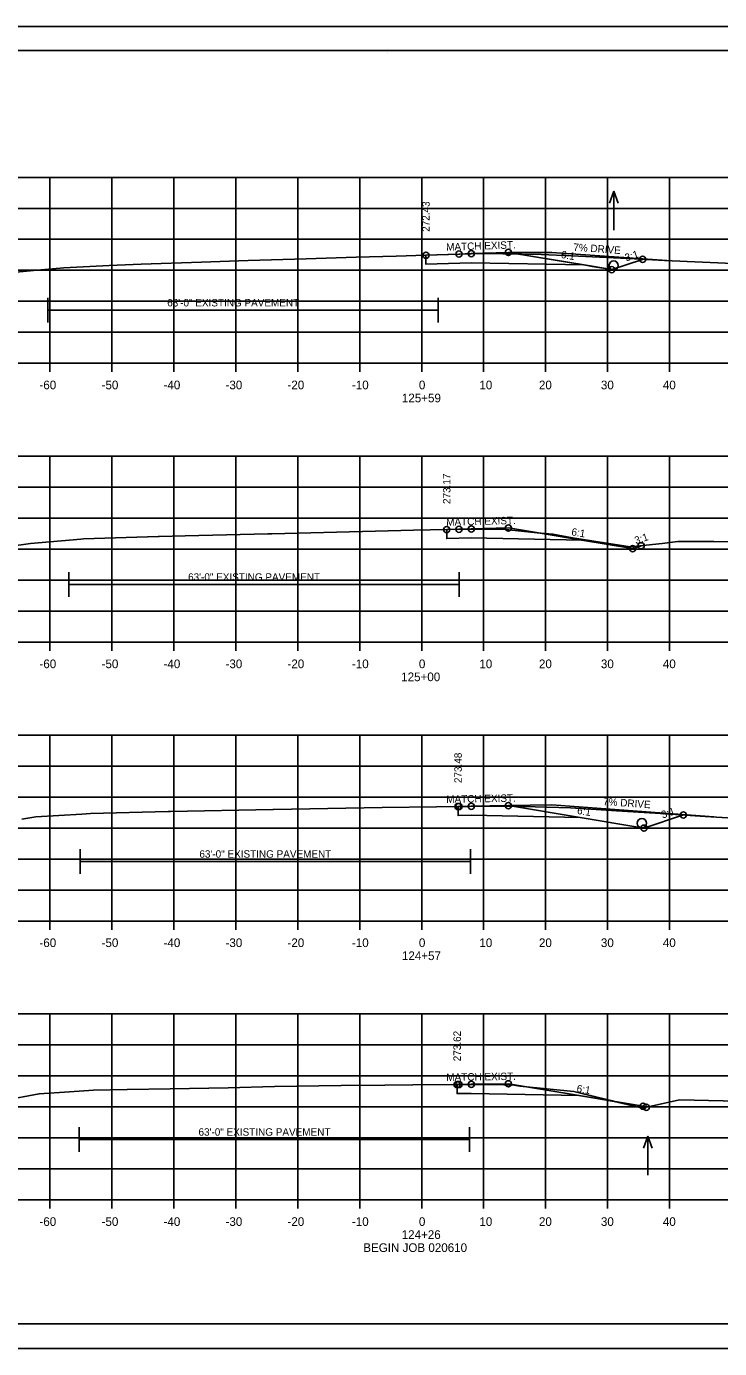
# Model space of a CAD drawing. Extents: x 1103485 to 1107180, y 2010593 to 2011873.
# Drawn here: x 1106953.4 to 1107065.3, y 2010592.8 to 2010806.2 of the extents above; entities that cross this region are included whole.
import ezdxf

# ---------------------------------------------------------------- set-up
doc = ezdxf.new("R2010")
doc.units = 0
for name, color, linetype in [('R_Alt Surface', 7, 'Continuous'), ('R_Axis', 7, 'Continuous'), ('R_Axis Annot', 7, 'Continuous'), ('R_Border', 7, 'Continuous'), ('R_Contours', 7, 'Continuous'), ('R_Dimension', 7, 'Continuous'), ('R_Drive', 7, 'Continuous'), ('R_Exist Surface', 7, 'Continuous'), ('R_Fin Surface', 7, 'Continuous'), ('R_Grid', 7, 'Continuous'), ('R_No Plot', 7, 'Continuous'), ('R_Proposed Const Limits', 7, 'Continuous'), ('R_Water', 7, 'Continuous'), ('R_Water Annot', 7, 'Continuous'), ('R_Xsect Elev', 7, 'Continuous'), ('R_Xsect Slope', 7, 'Continuous')]:
    doc.layers.add(name, color=color, linetype=linetype)

msp = doc.modelspace()

# ---------------------------------------------------------------- linework, layer by layer
at = {"layer": 'R_Alt Surface'}
for points in [[(1107017.86, 2010769.25), (1107017.86, 2010767.79), (1107025.18, 2010768.04), (1107043.38, 2010767.68)], [(1107021.22, 2010724.99), (1107021.22, 2010723.53), (1107025.18, 2010723.63), (1107043.02, 2010723.27)], [(1107023.05, 2010680.3), (1107023.05, 2010678.84), (1107025.18, 2010678.88), (1107042.73, 2010678.53)], [(1107022.9, 2010635.43), (1107022.9, 2010633.97), (1107025.18, 2010634.01), (1107042.6, 2010633.66)]]:
    msp.add_lwpolyline(points, dxfattribs=at)
at = {"layer": 'R_Axis'}
for p, q in [((1106867.18, 2010751.82), (1107167.18, 2010751.82)), ((1106957.18, 2010750.42), (1106957.18, 2010751.82)), ((1106967.18, 2010750.42), (1106967.18, 2010751.82)), ((1106977.18, 2010750.42), (1106977.18, 2010751.82)), ((1106987.18, 2010750.42), (1106987.18, 2010751.82)), ((1106997.18, 2010750.42), (1106997.18, 2010751.82)), ((1107007.18, 2010750.42), (1107007.18, 2010751.82)), ((1107017.18, 2010750.42), (1107017.18, 2010751.82)), ((1107027.18, 2010750.42), (1107027.18, 2010751.82)), ((1107037.18, 2010750.42), (1107037.18, 2010751.82)), ((1107047.18, 2010750.42), (1107047.18, 2010751.82)), ((1107057.18, 2010750.42), (1107057.18, 2010751.82)), ((1106867.18, 2010706.82), (1107167.18, 2010706.82)), ((1106957.18, 2010705.42), (1106957.18, 2010706.82)), ((1106967.18, 2010705.42), (1106967.18, 2010706.82)), ((1106977.18, 2010705.42), (1106977.18, 2010706.82)), ((1106987.18, 2010705.42), (1106987.18, 2010706.82)), ((1106997.18, 2010705.42), (1106997.18, 2010706.82)), ((1107007.18, 2010705.42), (1107007.18, 2010706.82)), ((1107017.18, 2010705.42), (1107017.18, 2010706.82)), ((1107027.18, 2010705.42), (1107027.18, 2010706.82)), ((1107037.18, 2010705.42), (1107037.18, 2010706.82)), ((1107047.18, 2010705.42), (1107047.18, 2010706.82)), ((1107057.18, 2010705.42), (1107057.18, 2010706.82)), ((1106867.18, 2010661.82), (1107167.18, 2010661.82)), ((1106957.18, 2010660.42), (1106957.18, 2010661.82)), ((1106967.18, 2010660.42), (1106967.18, 2010661.82)), ((1106977.18, 2010660.42), (1106977.18, 2010661.82)), ((1106987.18, 2010660.42), (1106987.18, 2010661.82)), ((1106997.18, 2010660.42), (1106997.18, 2010661.82)), ((1107007.18, 2010660.42), (1107007.18, 2010661.82)), ((1107017.18, 2010660.42), (1107017.18, 2010661.82)), ((1107027.18, 2010660.42), (1107027.18, 2010661.82)), ((1107037.18, 2010660.42), (1107037.18, 2010661.82)), ((1107047.18, 2010660.42), (1107047.18, 2010661.82)), ((1107057.18, 2010660.42), (1107057.18, 2010661.82)), ((1106867.18, 2010616.82), (1107167.18, 2010616.82)), ((1106957.18, 2010615.42), (1106957.18, 2010616.82)), ((1106967.18, 2010615.42), (1106967.18, 2010616.82)), ((1106977.18, 2010615.42), (1106977.18, 2010616.82)), ((1106987.18, 2010615.42), (1106987.18, 2010616.82)), ((1106997.18, 2010615.42), (1106997.18, 2010616.82)), ((1107007.18, 2010615.42), (1107007.18, 2010616.82)), ((1107017.18, 2010615.42), (1107017.18, 2010616.82)), ((1107027.18, 2010615.42), (1107027.18, 2010616.82)), ((1107037.18, 2010615.42), (1107037.18, 2010616.82)), ((1107047.18, 2010615.42), (1107047.18, 2010616.82)), ((1107057.18, 2010615.42), (1107057.18, 2010616.82))]:
    msp.add_line(p, q, dxfattribs=at)
at = {"layer": 'R_Border'}
for p, q in [((1106859.18, 2010802.28), (1107175.36, 2010802.28)), ((1107011.7, 2010802.02), (1107011.7, 2010802.02)), ((1107011.7, 2010802.02), (1107011.7, 2010802.02)), ((1107175.36, 2010596.82), (1106859.18, 2010596.82))]:
    msp.add_line(p, q, dxfattribs=at)
at = {"layer": 'R_Contours'}
for points in [[(1107017.86, 2010769.25), (1107026.97, 2010769.51), (1107027.06, 2010769.51), (1107027.15, 2010769.51), (1107036.46, 2010769.36), (1107041.33, 2010769.13), (1107051.53, 2010768.65), (1107052.83, 2010768.59), (1107047.86, 2010766.93), (1107044.67, 2010767.46), (1107043.38, 2010767.68), (1107025.18, 2010768.04), (1107017.86, 2010767.79)], [(1107021.22, 2010724.99), (1107021.41, 2010724.99), (1107030.24, 2010725.06), (1107035.8, 2010724.48), (1107038.36, 2010724.27), (1107041.52, 2010723.64), (1107050.8, 2010722.18), (1107052.6, 2010722.37), (1107051.22, 2010721.91), (1107043.02, 2010723.27), (1107025.18, 2010723.63), (1107021.22, 2010723.53)], [(1107023.05, 2010680.3), (1107023.11, 2010680.3), (1107024.86, 2010680.31), (1107031.29, 2010680.35), (1107031.7, 2010680.34), (1107041.21, 2010680.08), (1107048.6, 2010679.62), (1107055.7, 2010679.17), (1107059.42, 2010678.93), (1107053.05, 2010676.81), (1107042.73, 2010678.53), (1107025.18, 2010678.88), (1107023.05, 2010678.84)], [(1107022.9, 2010635.43), (1107030.45, 2010635.39), (1107031.71, 2010635.37), (1107033.03, 2010635.19), (1107041.76, 2010634.29), (1107048.22, 2010632.72), (1107042.6, 2010633.66), (1107025.18, 2010634.01), (1107022.9, 2010633.97)], [(1107048.22, 2010632.72), (1107051.97, 2010631.82), (1107052.79, 2010631.64), (1107053.23, 2010631.73), (1107053.42, 2010631.77), (1107052.9, 2010631.94)]]:
    msp.add_lwpolyline(points, close=True, dxfattribs=at)
at = {"layer": 'R_Dimension'}
for p, q in [((1106956.86, 2010762.39), (1106956.86, 2010758.39)), ((1107019.86, 2010762.39), (1107019.86, 2010758.39)), ((1106956.86, 2010760.39), (1107019.86, 2010760.39)), ((1106960.22, 2010718.13), (1106960.22, 2010714.13)), ((1107023.22, 2010718.13), (1107023.22, 2010714.13)), ((1106960.22, 2010716.13), (1107023.22, 2010716.13)), ((1106962.05, 2010673.44), (1106962.05, 2010669.44)), ((1107025.05, 2010673.44), (1107025.05, 2010669.44)), ((1106962.05, 2010671.44), (1107025.05, 2010671.44)), ((1106961.9, 2010628.58), (1106961.9, 2010624.58)), ((1107024.9, 2010628.58), (1107024.9, 2010624.58)), ((1106961.9, 2010626.58), (1107024.9, 2010626.58))]:
    msp.add_line(p, q, dxfattribs=at)
at = {"layer": 'R_Drive'}
for p, q in [((1107031.18, 2010769.71), (1107038.18, 2010769.71)), ((1107038.18, 2010769.71), (1107056.73, 2010768.42)), ((1107031.18, 2010680.45), (1107038.18, 2010680.58)), ((1107038.18, 2010680.58), (1107064.33, 2010678.62))]:
    msp.add_line(p, q, dxfattribs=at)
at = {"layer": 'R_Exist Surface'}
for points in [[(1106951.15, 2010766.45), (1106955.12, 2010766.83), (1106959.41, 2010767.22), (1106966.72, 2010767.59), (1106971.9, 2010767.83), (1106981.66, 2010768.15), (1106989.15, 2010768.38), (1106998.52, 2010768.68), (1107006.6, 2010768.92), (1107013.05, 2010769.1), (1107017.86, 2010769.25), (1107026.97, 2010769.51), (1107027.06, 2010769.51), (1107027.15, 2010769.51), (1107036.46, 2010769.36), (1107041.33, 2010769.13), (1107051.53, 2010768.65), (1107056.34, 2010768.43), (1107068.63, 2010767.86)], [(1106946.71, 2010721.7), (1106954.05, 2010722.75), (1106962.19, 2010723.44), (1106962.6, 2010723.48), (1106974.67, 2010723.88), (1106974.79, 2010723.88), (1106979.01, 2010723.98), (1106992.35, 2010724.31), (1106993.01, 2010724.32), (1107009.71, 2010724.73), (1107015.88, 2010724.87), (1107021.22, 2010724.99), (1107021.41, 2010724.99), (1107030.24, 2010725.06), (1107035.8, 2010724.48), (1107038.36, 2010724.27), (1107041.52, 2010723.64), (1107050.8, 2010722.18), (1107055.98, 2010722.72), (1107058.5, 2010723.08), (1107064.31, 2010723.05), (1107073.05, 2010722.93)], [(1106952.63, 2010678.25), (1106954.9, 2010678.62), (1106962.32, 2010679.09), (1106963.74, 2010679.19), (1106976.28, 2010679.48), (1106976.44, 2010679.49), (1106976.66, 2010679.49), (1106993.16, 2010679.79), (1106993.26, 2010679.79), (1107010.81, 2010680.16), (1107019.56, 2010680.26), (1107023.05, 2010680.3), (1107023.11, 2010680.3), (1107024.86, 2010680.31), (1107031.29, 2010680.35), (1107031.7, 2010680.34), (1107041.21, 2010680.08), (1107048.6, 2010679.62), (1107055.7, 2010679.17), (1107062.95, 2010678.71), (1107070.17, 2010678.25)], [(1106949.69, 2010632.86), (1106955.43, 2010633.96), (1106960.33, 2010634.27), (1106964.21, 2010634.51), (1106969.63, 2010634.61), (1106976.57, 2010634.74), (1106985.95, 2010634.93), (1106993.44, 2010635.1), (1107004.2, 2010635.28), (1107011.22, 2010635.36), (1107015.74, 2010635.38), (1107022.9, 2010635.43), (1107030.45, 2010635.39), (1107031.71, 2010635.37), (1107033.03, 2010635.19), (1107041.76, 2010634.29), (1107051.97, 2010631.82), (1107052.79, 2010631.64), (1107053.23, 2010631.73), (1107058.8, 2010632.98), (1107070.52, 2010632.72)]]:
    msp.add_lwpolyline(points, dxfattribs=at)
at = {"layer": 'R_Fin Surface'}
for points in [[(1107017.86, 2010769.25), (1107023.18, 2010769.44), (1107025.18, 2010769.51), (1107031.18, 2010769.71), (1107043.38, 2010767.68), (1107047.86, 2010766.93), (1107052.83, 2010768.59)], [(1107017.86, 2010769.25), (1107023.18, 2010769.44), (1107025.18, 2010769.51), (1107031.18, 2010769.71)], [(1107021.22, 2010724.99), (1107023.18, 2010725.04), (1107025.18, 2010725.09), (1107031.18, 2010725.25), (1107043.02, 2010723.27), (1107051.22, 2010721.91), (1107052.6, 2010722.37)], [(1107021.22, 2010724.99), (1107023.18, 2010725.04), (1107025.18, 2010725.09), (1107031.18, 2010725.25)], [(1107023.05, 2010680.3), (1107023.18, 2010680.3), (1107025.18, 2010680.34), (1107031.18, 2010680.45), (1107042.73, 2010678.53), (1107053.05, 2010676.81), (1107059.42, 2010678.93)], [(1107023.05, 2010680.3), (1107023.18, 2010680.3), (1107025.18, 2010680.34), (1107031.18, 2010680.45)], [(1107022.9, 2010635.43), (1107023.18, 2010635.44), (1107025.18, 2010635.47), (1107031.18, 2010635.56), (1107042.6, 2010633.66), (1107052.9, 2010631.94), (1107053.42, 2010631.77)], [(1107022.9, 2010635.43), (1107023.18, 2010635.44), (1107025.18, 2010635.47), (1107031.18, 2010635.56)]]:
    msp.add_lwpolyline(points, dxfattribs=at)
at = {"layer": 'R_Grid'}
for p, q in [((1106867.18, 2010781.82), (1107167.18, 2010781.82)), ((1106957.18, 2010751.82), (1106957.18, 2010781.82)), ((1106967.18, 2010751.82), (1106967.18, 2010781.82)), ((1106977.18, 2010751.82), (1106977.18, 2010781.82)), ((1106987.18, 2010751.82), (1106987.18, 2010781.82)), ((1106997.18, 2010751.82), (1106997.18, 2010781.82)), ((1107007.18, 2010751.82), (1107007.18, 2010781.82)), ((1107017.18, 2010751.82), (1107017.18, 2010781.82)), ((1107027.18, 2010751.82), (1107027.18, 2010781.82)), ((1107037.18, 2010751.82), (1107037.18, 2010781.82)), ((1107047.18, 2010751.82), (1107047.18, 2010781.82)), ((1107057.18, 2010751.82), (1107057.18, 2010781.82)), ((1106867.18, 2010776.82), (1107167.18, 2010776.82)), ((1106867.18, 2010771.82), (1107167.18, 2010771.82)), ((1106867.18, 2010766.82), (1107167.18, 2010766.82)), ((1106867.18, 2010761.82), (1107167.18, 2010761.82)), ((1106867.18, 2010756.82), (1107167.18, 2010756.82)), ((1106867.18, 2010751.82), (1107167.18, 2010751.82)), ((1106867.18, 2010736.82), (1107167.18, 2010736.82)), ((1106957.18, 2010706.82), (1106957.18, 2010736.82)), ((1106967.18, 2010706.82), (1106967.18, 2010736.82)), ((1106977.18, 2010706.82), (1106977.18, 2010736.82)), ((1106987.18, 2010706.82), (1106987.18, 2010736.82)), ((1106997.18, 2010706.82), (1106997.18, 2010736.82)), ((1107007.18, 2010706.82), (1107007.18, 2010736.82)), ((1107017.18, 2010706.82), (1107017.18, 2010736.82)), ((1107027.18, 2010706.82), (1107027.18, 2010736.82)), ((1107037.18, 2010706.82), (1107037.18, 2010736.82)), ((1107047.18, 2010706.82), (1107047.18, 2010736.82)), ((1107057.18, 2010706.82), (1107057.18, 2010736.82)), ((1106867.18, 2010731.82), (1107167.18, 2010731.82)), ((1106867.18, 2010726.82), (1107167.18, 2010726.82)), ((1106867.18, 2010721.82), (1107167.18, 2010721.82)), ((1106867.18, 2010716.82), (1107167.18, 2010716.82)), ((1106867.18, 2010711.82), (1107167.18, 2010711.82)), ((1106867.18, 2010706.82), (1107167.18, 2010706.82)), ((1106867.18, 2010691.82), (1107167.18, 2010691.82)), ((1106957.18, 2010661.82), (1106957.18, 2010691.82)), ((1106967.18, 2010661.82), (1106967.18, 2010691.82)), ((1106977.18, 2010661.82), (1106977.18, 2010691.82)), ((1106987.18, 2010661.82), (1106987.18, 2010691.82)), ((1106997.18, 2010661.82), (1106997.18, 2010691.82)), ((1107007.18, 2010661.82), (1107007.18, 2010691.82)), ((1107017.18, 2010661.82), (1107017.18, 2010691.82)), ((1107027.18, 2010661.82), (1107027.18, 2010691.82)), ((1107037.18, 2010661.82), (1107037.18, 2010691.82)), ((1107047.18, 2010661.82), (1107047.18, 2010691.82)), ((1107057.18, 2010661.82), (1107057.18, 2010691.82)), ((1106867.18, 2010686.82), (1107167.18, 2010686.82)), ((1106867.18, 2010681.82), (1107167.18, 2010681.82)), ((1106867.18, 2010676.82), (1107167.18, 2010676.82)), ((1106867.18, 2010671.82), (1107167.18, 2010671.82)), ((1106867.18, 2010666.82), (1107167.18, 2010666.82)), ((1106867.18, 2010661.82), (1107167.18, 2010661.82)), ((1106867.18, 2010646.82), (1107167.18, 2010646.82)), ((1106957.18, 2010616.82), (1106957.18, 2010646.82)), ((1106967.18, 2010616.82), (1106967.18, 2010646.82)), ((1106977.18, 2010616.82), (1106977.18, 2010646.82)), ((1106987.18, 2010616.82), (1106987.18, 2010646.82)), ((1106997.18, 2010616.82), (1106997.18, 2010646.82)), ((1107007.18, 2010616.82), (1107007.18, 2010646.82)), ((1107017.18, 2010616.82), (1107017.18, 2010646.82)), ((1107027.18, 2010616.82), (1107027.18, 2010646.82)), ((1107037.18, 2010616.82), (1107037.18, 2010646.82)), ((1107047.18, 2010616.82), (1107047.18, 2010646.82)), ((1107057.18, 2010616.82), (1107057.18, 2010646.82)), ((1106867.18, 2010641.82), (1107167.18, 2010641.82)), ((1106867.18, 2010636.82), (1107167.18, 2010636.82)), ((1106867.18, 2010631.82), (1107167.18, 2010631.82)), ((1106867.18, 2010626.82), (1107167.18, 2010626.82)), ((1106867.18, 2010621.82), (1107167.18, 2010621.82)), ((1106867.18, 2010616.82), (1107167.18, 2010616.82))]:
    msp.add_line(p, q, dxfattribs=at)
at = {"layer": 'R_No Plot'}
for p, q in [((1106846.78, 2010806.17), (1107180.12, 2010806.17)), ((1106846.78, 2010592.84), (1107180.12, 2010592.84))]:
    msp.add_line(p, q, dxfattribs=at)
for points in [[(1106846.78, 2010806.17), (1107180.12, 2010806.17), (1107180.12, 2010592.83), (1106846.78, 2010592.83)], [(1107093.1, 2010802.28), (1107093.1, 2010792.4), (1107128.84, 2010792.4), (1107128.84, 2010789.48), (1107152.04, 2010789.48), (1107152.04, 2010765.14), (1107175.36, 2010765.14), (1107175.36, 2010596.82), (1106859.18, 2010596.82), (1106859.18, 2010802.28)]]:
    msp.add_lwpolyline(points, close=True, dxfattribs=at)
for centre in [(1107017.86, 2010769.25), (1107023.18, 2010769.44), (1107025.18, 2010769.51), (1107031.18, 2010769.71), (1107052.83, 2010768.59), (1107047.86, 2010766.93), (1107021.22, 2010724.99), (1107023.18, 2010725.04), (1107025.18, 2010725.09), (1107031.18, 2010725.25), (1107051.22, 2010721.91), (1107052.6, 2010722.37), (1107023.05, 2010680.3), (1107023.18, 2010680.3), (1107025.18, 2010680.34), (1107031.18, 2010680.45), (1107059.42, 2010678.93), (1107053.05, 2010676.81), (1107022.9, 2010635.43), (1107023.18, 2010635.44), (1107025.18, 2010635.47), (1107031.18, 2010635.56), (1107052.9, 2010631.94), (1107053.42, 2010631.77)]:
    msp.add_circle(centre, 0.5, dxfattribs=at)
at = {"layer": 'R_Proposed Const Limits'}
for points in [[(1107031.18, 2010769.71), (1107047.86, 2010766.93), (1107052.83, 2010768.59)], [(1107031.18, 2010725.25), (1107051.22, 2010721.91), (1107052.6, 2010722.37)], [(1107031.18, 2010680.45), (1107053.05, 2010676.81), (1107059.42, 2010678.93)], [(1107031.18, 2010635.56), (1107052.9, 2010631.94), (1107053.42, 2010631.77)]]:
    msp.add_lwpolyline(points, dxfattribs=at)
at = {"layer": 'R_Water'}
for centre, radius in [((1107048.16, 2010767.58), 0.75), ((1107048.16, 2010767.58), 0.755), ((1107052.72, 2010677.6), 0.755), ((1107052.72, 2010677.6), 0.75)]:
    msp.add_circle(centre, radius, dxfattribs=at)
at = {"layer": 'R_Water Annot'}
for p, q in [((1107048.18, 2010779.6), (1107047.48, 2010777.67)), ((1107048.18, 2010773.31), (1107048.18, 2010779.6)), ((1107048.18, 2010779.6), (1107048.88, 2010777.67)), ((1107053.7, 2010627.09), (1107053, 2010625.16)), ((1107053.7, 2010620.8), (1107053.7, 2010627.09)), ((1107053.7, 2010627.09), (1107054.4, 2010625.16))]:
    msp.add_line(p, q, dxfattribs=at)

# ---------------------------------------------------------------- texts
at = {"layer": 'R_Axis Annot'}
for s, p in [('-60', (1106955.49, 2010747.62)), ('-50', (1106965.52, 2010747.62)), ('-40', (1106975.52, 2010747.62)), ('-30', (1106985.52, 2010747.62)), ('-20', (1106995.52, 2010747.62)), ('-10', (1107005.92, 2010747.62)), ('0', (1107016.73, 2010747.62)), ('10', (1107026.49, 2010747.62)), ('20', (1107036.1, 2010747.62)), ('30', (1107046.1, 2010747.62)), ('40', (1107056.1, 2010747.62)), ('125+59', (1107013.98, 2010745.52)), ('-60', (1106955.49, 2010702.62)), ('-50', (1106965.52, 2010702.62)), ('-40', (1106975.52, 2010702.62)), ('-30', (1106985.52, 2010702.62)), ('-20', (1106995.52, 2010702.62)), ('-10', (1107005.92, 2010702.62)), ('0', (1107016.73, 2010702.62)), ('10', (1107026.49, 2010702.62)), ('20', (1107036.1, 2010702.62)), ('30', (1107046.1, 2010702.62)), ('40', (1107056.1, 2010702.62)), ('125+00', (1107013.87, 2010700.52)), ('-60', (1106955.49, 2010657.62)), ('-50', (1106965.52, 2010657.62)), ('-40', (1106975.52, 2010657.62)), ('-30', (1106985.52, 2010657.62)), ('-20', (1106995.52, 2010657.62)), ('-10', (1107005.92, 2010657.62)), ('0', (1107016.73, 2010657.62)), ('10', (1107026.49, 2010657.62)), ('20', (1107036.1, 2010657.62)), ('30', (1107046.1, 2010657.62)), ('40', (1107056.1, 2010657.62)), ('124+57', (1107013.99, 2010655.52)), ('-60', (1106955.49, 2010612.62)), ('-50', (1106965.52, 2010612.62)), ('-40', (1106975.52, 2010612.62)), ('-30', (1106985.52, 2010612.62)), ('-20', (1106995.52, 2010612.62)), ('-10', (1107005.92, 2010612.62)), ('0', (1107016.73, 2010612.62)), ('10', (1107026.49, 2010612.62)), ('20', (1107036.1, 2010612.62)), ('30', (1107046.1, 2010612.62)), ('40', (1107056.1, 2010612.62)), ('124+26', (1107013.95, 2010610.52)), ('BEGIN JOB 020610', (1107007.75, 2010608.42))]:
    msp.add_text(s, height=1.4, dxfattribs=at).set_placement(p)
at = {"layer": 'R_Dimension'}
for p in [(1106976.11, 2010760.99), (1106979.48, 2010716.73), (1106981.3, 2010672.04), (1106981.16, 2010627.18)]:
    msp.add_text('63\'-0" EXISTING PAVEMENT', height=1.2, dxfattribs=at).set_placement(p)
at = {"layer": 'R_Drive'}
for p in [(1107041.62, 2010769.98), (1107046.43, 2010680.54)]:
    msp.add_text('7% DRIVE', height=1.2, rotation=355.996, dxfattribs=at).set_placement(p)
at = {"layer": 'R_Xsect Elev'}
for s, p in [('272.43', (1107018.46, 2010773.03)), ('273.17', (1107021.82, 2010729.11)), ('273.48', (1107023.65, 2010684.08)), ('273.62', (1107023.5, 2010639.19))]:
    msp.add_text(s, height=1.2, rotation=90, dxfattribs=at).set_placement(p)
at = {"layer": 'R_Xsect Slope'}
for s, rotation, p in [('MATCH EXIST.', 1.9876, (1107021.15, 2010769.97)), ('6:1', 350.5358, (1107039.6, 2010768.82)), ('3:1', 18.4332, (1107050.19, 2010768.24)), ('MATCH EXIST.', 1.4791, (1107021.15, 2010725.59)), ('6:1', 350.5358, (1107041.28, 2010724.07)), ('3:1', 18.4332, (1107051.75, 2010722.61)), ('MATCH EXIST.', 1.0726, (1107021.15, 2010680.87)), ('6:1', 350.5358, (1107042.2, 2010679.12)), ('3:1', 18.4332, (1107056.07, 2010678.35)), ('MATCH EXIST.', 0.8971, (1107021.16, 2010636.01)), ('6:1', 350.5358, (1107042.12, 2010634.25))]:
    msp.add_text(s, height=1.2, rotation=rotation, dxfattribs=at).set_placement(p)

doc.saveas('drawing.dxf')
